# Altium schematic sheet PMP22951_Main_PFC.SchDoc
size 431 x 279 mm; Date: Not shown in title block; ApprovedBy: Not shown in title block; CheckedBy: Not shown in title block; Author: Not shown in title block; CompanyName: Not shown in title block; Engineer: Not shown in title block; Organization: Not shown in title block; Address1: Not shown in title block; Address2: Not shown in title block; Address3: Not shown in title block; Address4: Not shown in title block; DocumentNumber: 1; Revision: Use project parameter SCH_Rev; SheetNumber: 1; SheetTotal: 4; PageSetup: Record=PageOptions¦CenterHorizontal=True¦CenterVertical=True¦PrintScale=1.00¦XCorrection=1.00¦YCorrection=1.00¦PrintKind=0¦BorderSize=5000000¦LeftOffset=0¦BottomOffset=0¦Orientation=2¦PaperLength=1000¦PaperWidth=1000¦Scale=100¦PaperSource=15¦PrintQuality=600¦MediaType=1¦DitherType=10¦PaperKind=Letter¦PrintScaleMode=1
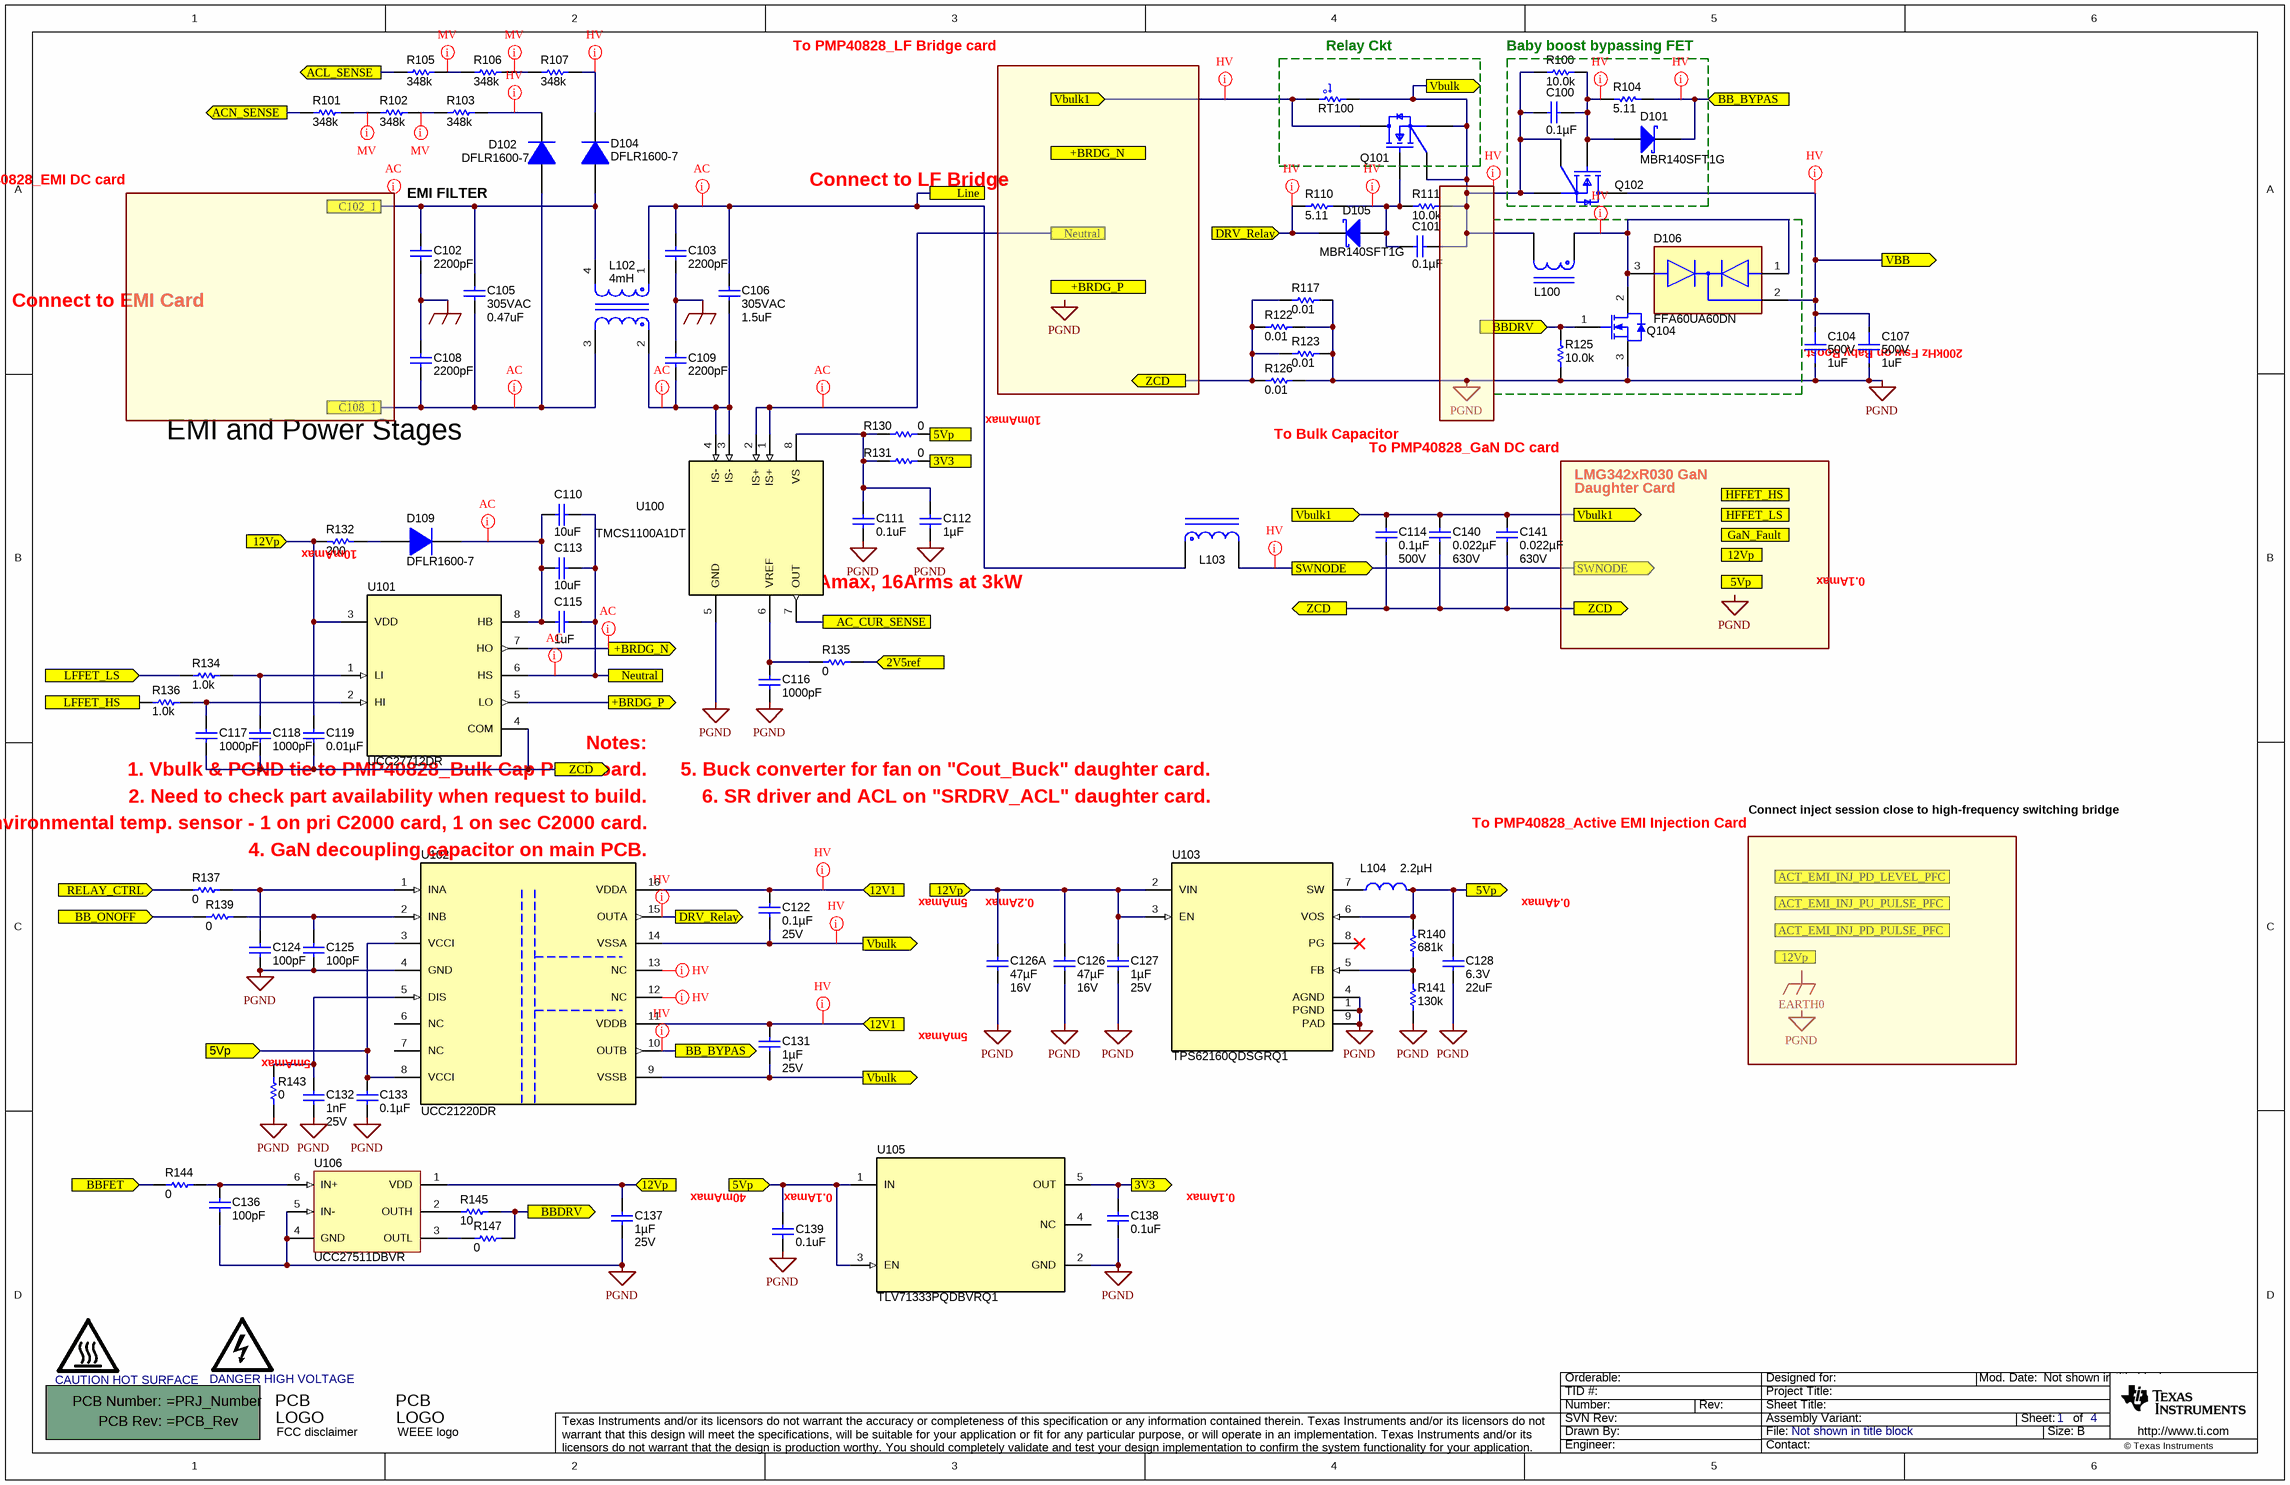
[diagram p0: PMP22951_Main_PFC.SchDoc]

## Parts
!PCB100  Printed Circuit Board  (value not drawn)  (mechanical)
C100  ValueDisplayed: 0.1µF  [0603]  (hidden comment: 06033C104JAT2A)
C101  ValueDisplayed: 0.1µF  [0603]  (hidden comment: 06033C104JAT2A)
C102  ValueDisplayed: 2200pF  [E_900x700x900]  (hidden comment: DE6E3KJ222MN3A)
C103  ValueDisplayed: 2200pF  [E_900x700x900]  (hidden comment: DE6E3KJ222MN3A)
C104  VDC_V: 500V  ValueDisplayed: 1uF  [FP-B58031U5105M062_SMD2-MFG]  (hidden comment: B58031U5105M062)
C105  Value2: 305VAC  ValueDisplayed: 0.47uF  [B32923_16.5mm_10.5]  (hidden comment: B32923H3474K000)
C106  Value2: 305VAC  ValueDisplayed: 1.5uF  [B32923_29.5mm]  (hidden comment: B32923H3155K000)
C107  VDC_V: 500V  ValueDisplayed: 1uF  [FP-B58031U5105M062_SMD2-MFG]  (hidden comment: B58031U5105M062)
C108  ValueDisplayed: 2200pF  [E_900x700x900]  (hidden comment: DE6E3KJ222MN3A)
C109  ValueDisplayed: 2200pF  [E_900x700x900]  (hidden comment: DE6E3KJ222MN3A)
C110  ValueDisplayed: 10uF  [0805_HV]  (hidden comment: 0805YD106MAT2A)
C111  ValueDisplayed: 0.1uF  [0402]  (hidden comment: GRM155R70J104KA01D)
C112  ValueDisplayed: 1µF  [0603]  (hidden comment: GRM185R60J105KE26D)
C113  ValueDisplayed: 10uF  [0805_HV]  (hidden comment: 0805YD106MAT2A)
C114  ValueDisplayed: 0.1µF  Value2: 500V  [1812]  (hidden comment: VJ1812Y104KXEAT5Z)
C115  ValueDisplayed: 1uF  [0603]  (hidden comment: C1608X7R1E105K080AB)
C116  ValueDisplayed: 1000pF  [0402]  (hidden comment: GRM155R60J102KA01D)
C117  ValueDisplayed: 1000pF  [0603]  (hidden comment: 06035A102KAT2A)
C118  ValueDisplayed: 1000pF  [0603]  (hidden comment: 06035A102KAT2A)
C119  ValueDisplayed: 0.01µF  [0603]  (hidden comment: C0603X103K5RACTU)
C122  ValueDisplayed: 0.1µF  Value2: 25V  [0603]  (hidden comment: 06033C104JAT2A)
C124  ValueDisplayed: 100pF  [0402]  (hidden comment: 0402YC101KAT2A)
C125  ValueDisplayed: 100pF  [0402]  (hidden comment: 0402YC101KAT2A)
C126  ValueDisplayed: 47µF  Value2: 16V  [1210_270]  (hidden comment: GRM32ER61C476KE15L)
C126A  ValueDisplayed: 47µF  Value2: 16V  [1210_270]  (hidden comment: GRM32ER61C476KE15L)
C127  Cap_F: 1µF  VDC_V: 25V  [0805_HV]  (hidden comment: C0805C105K3RACTU)
C128  VDC_V: 6.3V  ValueDisplayed: 22uF  [0805_HV]  (hidden comment: CL21A226KQQNNNE)
C131  ValueDisplayed: 1µF  Value2: 25V  [1206]  (hidden comment: C3216X7R1E105K085AA)
C132  Cap_F: 1nF  VDC_V: 25V  [0603]  (hidden comment: GRM188R71E102KA01D)
C133  ValueDisplayed: 0.1µF  [0402]  (hidden comment: 0402YC104KAT2A)
C136  ValueDisplayed: 100pF  [0402]  (hidden comment: 0402YC101KAT2A)
C137  ValueDisplayed: 1µF  Value2: 25V  [1206]  (hidden comment: C3216X7R1E105K085AA)
C138  ValueDisplayed: 0.1uF  [0402]  (hidden comment: GRM155R70J104KA01D)
C139  ValueDisplayed: 0.1uF  [0402]  (hidden comment: GRM155R70J104KA01D)
C140  ValueDisplayed: 0.022µF  Value2: 630V  [1206]  (hidden comment: CL31B223KHHNNNE)
C141  ValueDisplayed: 0.022µF  Value2: 630V  [1206]  (hidden comment: CL31B223KHHNNNE)
D101  MBR140SFT1G  [SOD-123FL]
D102  DFLR1600-7  [PowerDI123]
D104  DFLR1600-7  [PowerDI123]
D105  MBR140SFT1G  [SOD-123FL]
D106  FFA60UA60DN  [FP-FFA60UA60DN_SC-65-MFG]
D109  DFLR1600-7  [PowerDI123]
L100  PAL6281.104NL  [FP-PAL6281.104NL_PTH_20MM5_11MM0-MFG]  (value not drawn)
L102  Ind_H: 4mH  [FP-PAC6270NL_PTH_TRANSFORMER_30MM0_19MM0-MFG]  (hidden comment: PAC6270NL)
L103  PAL6269NL  [FP-PAL6269NL_PTH_32MM0_27MM8-MFG]  (value not drawn)
L104  Ind_H: 2.2µH  [FP-74438336010_SMD2-MFG]  (hidden comment: 74438336022)
LOGO100  CAUTION HOT SURFACE  [IEC_HotSurface_Small]  (no BOM)
LOGO101  DANGER HIGH VOLTAGE  [IEC_HighVoltage_Small]  (no BOM)
Logo102  FCC disclaimer  [FCC_disclaimer]  (no BOM)
Logo103  WEEE logo  [WEEE_Minimum]  (no BOM)
Q101  IPT60R022S7XTMA1  [FP-IPT60R080G7XTMA1_HSOF-8-MFG]  (value not drawn)
Q102  IPT60R022S7XTMA1  [FP-IPT60R080G7XTMA1_HSOF-8-MFG]  (value not drawn)
Q104  IPP60R060P7XKSA1  [TO-220AB]  (value not drawn)
R100  ValueDisplayed: 10.0k  [0603]  (hidden comment: CRCW060310K0FKEA)
R101  ValueDisplayed: 348k  [1206]  (hidden comment: RC1206FR-07348KL)
R102  ValueDisplayed: 348k  [1206]  (hidden comment: RC1206FR-07348KL)
R103  ValueDisplayed: 348k  [1206]  (hidden comment: RC1206FR-07348KL)
R104  ValueDisplayed: 5.11  [0603]  (hidden comment: CRCW06035R11FKEA)
R105  ValueDisplayed: 348k  [1206]  (hidden comment: RC1206FR-07348KL)
R106  ValueDisplayed: 348k  [1206]  (hidden comment: RC1206FR-07348KL)
R107  ValueDisplayed: 348k  [1206]  (hidden comment: RC1206FR-07348KL)
R110  ValueDisplayed: 5.11  [1206]  (hidden comment: CRCW12065R11FKEA)
R111  ValueDisplayed: 10.0k  [0603]  (hidden comment: CRCW060310K0FKEA)
R117  ValueDisplayed: 0.01  [1206]  (hidden comment: CSR1206FK10L0)
R122  ValueDisplayed: 0.01  [1206]  (hidden comment: CSR1206FK10L0)
R123  ValueDisplayed: 0.01  [1206]  (hidden comment: CSR1206FK10L0)
R125  ValueDisplayed: 10.0k  [0603]  (hidden comment: CRCW060310K0FKEA)
R126  ValueDisplayed: 0.01  [1206]  (hidden comment: CSR1206FK10L0)
R130  ValueDisplayed: 0  [0402]  (hidden comment: RC0402JR-070RL)
R131  ValueDisplayed: 0  [0402]  (hidden comment: RC0402JR-070RL)
R132  value 200  [0603]  (hidden comment: CRCW0603200RFKEA)
R134  value 1.0k  [0402]  (hidden comment: CRCW04021K00JNED)
R135  ValueDisplayed: 0  [0402]  (hidden comment: RC0402JR-070RL)
R136  value 1.0k  [0402]  (hidden comment: CRCW04021K00JNED)
R137  ValueDisplayed: 0  [0402]  (hidden comment: CRCW04020000Z0ED)
R139  ValueDisplayed: 0  [0402]  (hidden comment: CRCW04020000Z0ED)
R140  ValueDisplayed: 681k  [0402]  (hidden comment: CRCW0402681KFKED)
R141  ValueDisplayed: 130k  [0402]  (hidden comment: CRCW0402130KFKED)
R143  ValueDisplayed: 0  [0603]  (hidden comment: CRCW06030000Z0EA)
R144  ValueDisplayed: 0  [0402]  (hidden comment: CRCW04020000Z0ED)
R145  ValueDisplayed: 10  [0603]  (hidden comment: CRCW060310R0JNEAHP)
R147  ValueDisplayed: 0  [0603]  (hidden comment: CRCW06030000Z0EA)
RT100  B59751B0120A070  [TDK_B751]  (value not drawn)
U100  TMCS1100A1DT  [D0008A_N]
U101  UCC27712DR  [D0008A_N]
U102  UCC21220DR  [D0016B]
U103  TPS62160QDSGRQ1  [DSG0008A]
U105  TLV71333PQDBVRQ1  [DBV0005A_N]
U106  UCC27511DBVR  [DBV0006A_N]

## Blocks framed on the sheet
Relay Ckt: Q101 RT100
Baby boost bypassing FET: C100 D101 Q102 R100 R104

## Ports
2V5ref (in), 3V3 (in), 3V3 (out), 5Vp (in), 5Vp (out), 12V1 (in), 12Vp (in), +BRDG_N (in), +BRDG_N (out), +BRDG_P (in), +BRDG_P (out), AC_CUR_SENSE, ACL_SENSE (out), ACN_SENSE (out), ACT_EMI_INJ_PD_LEVEL_PFC (in), ACT_EMI_INJ_PD_PULSE_PFC (in), ACT_EMI_INJ_PU_PULSE_PFC (in), BB_BYPAS (in), BB_BYPAS (out), BB_ONOFF (in), BBDRV (in), BBDRV (out), BBFET (in), C102_1, C108_1, DRV_Relay (in), DRV_Relay (out), GaN_Fault (out), HFFET_HS (in), HFFET_LS (in), LFFET_HS (in), LFFET_LS (in), Line, Neutral, RELAY_CTRL (in), SWNODE (out), VBB (out), Vbulk1 (in), Vbulk1 (out), Vbulk (out), ZCD (out)

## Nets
EARTH0: C102.2 C108.1
EARTH1: C103.2 C109.1
PGND: C104.1 C107.1 C111.2 C112.2 C116.2 C124.2 C125.2 C126.1 C126A.1 C127.2 C128.2 C132.2 C133.2 C136.2 C137.2 C138.2 C139.2 Q104.3(S) R117.2 R122.2 R123.2 R125.1 R126.2 R141.1 R143.1 U100.5(GND) U102.4(GND) U103.1(PGND) U103.4(AGND) U103.9(PAD) U105.2(GND) U106.4(GND) U106.5(IN-)
2V5ref: R135.2 ; port 2V5ref
3V3: C138.1 R131.2 U105.5(OUT) ; port 3V3
5Vp: C128.1 C133.1 C139.1 L104.2 R130.2 R140.2 U102.3(VCCI) U102.8(VCCI) U103.6(VOS) U105.1(IN) U105.3(EN) ; port 5Vp
12V1: C122.2 C131.1 U102.11(VDDB) U102.16(VDDA) ; port 12V1
12Vp: C119.1 C126.2 C126A.2 C127.1 C137.1 R132.2 U101.3(VDD) U103.2(VIN) U103.3(EN) U106.1(VDD) ; port 12Vp
+BRDG_N: U101.7(HO) ; port +BRDG_N
+BRDG_P: U101.5(LO) ; port +BRDG_P
AC_CUR_SENSE: U100.7(OUT) ; port AC_CUR_SENSE
ACL_SENSE: R105.1 ; port ACL_SENSE
ACN_SENSE: R101.1 ; port ACN_SENSE
BB_BYPAS: D101.1(K) R104.2 U102.10(OUTB) ; port BB_BYPAS
BB_ONOFF: R139.1 ; port BB_ONOFF
BBDRV: Q104.1(G) R125.2 R145.1 R147.2 ; port BBDRV
BBFET: R144.1 ; port BBFET
C102_1: C102.1 C105.1 D104.2(A) L102.4 ; port C102_1
C108_1: C105.2 C108.2 D102.2(A) L102.3 ; port C108_1
DRV_Relay: D105.1(K) R110.1 U102.15(OUTA) ; port DRV_Relay
LFFET_HS: R136.1 ; port LFFET_HS
LFFET_LS: R134.1 ; port LFFET_LS
Line: C103.1 C106.1 L102.1 L103.1 ; port Line
Neutral: C110.2 C113.2 C115.1 U100.1(IS+) U100.2(IS+) U101.6(HS) ; port Neutral
RELAY_CTRL: R137.1 ; port RELAY_CTRL
SWNODE: L103.2 ; port SWNODE
VBB: C104.2 C107.2 D106.2(COMMON_CATHODE) Q102.9(Drain) ; port VBB
Vbulk: C100.2 C101.1 C122.1 C131.2 L100.2(F) Q101.2(Driver_Source) Q101.3-4-5-6-7-8(Source) Q102.2(Driver_Source) Q102.3-4-5-6-7-8(Source) R100.1 R111.2 RT100.1 U102.9(VSSB) U102.14(VSSA) ; port Vbulk
Vbulk1: C114.1 C140.1 C141.1 Q101.9(Drain) RT100.2 ; port Vbulk1
ZCD: C114.2 C117.2 C118.2 C119.2 C140.2 C141.2 R117.1 R122.1 R123.1 R126.1 U101.4(COM) ; port ZCD
NetC100_1: C100.1 D101.2(A) Q102.1(Gate) R100.2 R104.1
NetC101_2: C101.2 D105.2(A) Q101.1(Gate) R110.2 R111.1
NetC106_2: C106.2 C109.2 L102.2 U100.3(IS-) U100.4(IS-)
NetC110_1: C110.1 C113.1 C115.2 D109.1(K) U101.8(HB)
NetC111_1: C111.1 C112.1 R130.1 R131.1 U100.8(VS)
NetC116_1: C116.1 R135.1 U100.6(VREF)
NetC117_1: C117.1 R136.2 U101.2(HI)
NetC118_1: C118.1 R134.2 U101.1(LI)
NetC124_1: C124.1 R137.2 U102.1(INA)
NetC125_1: C125.1 R139.2 U102.2(INB)
NetC132_1: C132.1 R143.2 U102.5(DIS)
NetC136_1: C136.1 R144.2 U106.6(IN+)
NetD102_1: D102.1(K) R103.2
NetD104_1: D104.1(K) R107.2
NetD106_1: D106.1(1_ANODE) D106.3(2_ANODE) L100.1(S) Q104.2(D)
NetD109_2: D109.2(A) R132.1
NetL104_1: L104.1 U103.7(SW)
NetR101_2: R101.2 R102.1
NetR102_2: R102.2 R103.1
NetR105_2: R105.2 R106.1
NetR106_2: R106.2 R107.1
NetR140_1: R140.1 R141.2 U103.5(FB)
NetR145_2: R145.2 U106.2(OUTH)
NetR147_1: R147.1 U106.3(OUTL)

Not connected (* = marked no-connect by the designer): U102 6(NC) 7(NC) 12(NC) 13(NC); U103 8(PG)*; U105 4(NC)

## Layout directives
net class AC: +BRDG_N, C102_1, C108_1, Line, NetC106_2, NetC110_1, Neutral
net class HV: 12V1, BB_BYPAS, DRV_Relay, NetC100_1, NetC101_2, NetD102_1, NetD104_1, NetD106_1, NetU102_12, NetU102_13, SWNODE, VBB, Vbulk, Vbulk1
net class MV: NetR101_2, NetR102_2, NetR105_2, NetR106_2

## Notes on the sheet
- To PMP40828_LF Bridge card
- To PMP40828_EMI DC card
- EMI FILTER
- Connect to LF Bridge
- Connect to EMI Card
- (near C104) 200kHz Fsw on Baby Boost.
- 10mAmax
- To Bulk Capacitor
- (near C108) EMI and Power Stages
- To PMP40828_GaN DC card
- LMG342xR030 GaN
- Daughter Card
- (near R132) 10mAmax
- (near L103) 200uH, 25Amax, 16Arms at 3kW
- 0.1Amax
- Notes:
- 1. Vbulk & PGND tie to PMP40828_Bulk Cap PCB board.
- 5. Buck converter for fan on "Cout_Buck" daughter card.
- 2. Need to check part availability when request to build.
- 3. Need environmental temp. sensor - 1 on pri C2000 card, 1 on sec C2000 card.
- 6. SR driver and ACL on "SRDRV_ACL" daughter card.
- To PMP40828_Active EMI Injection Card
- Connect inject session close to high-frequency switching bridge
- 4. GaN decoupling capacitor on main PCB.
- 5mAmax
- (near C126A) 0.2Amax
- 0.4Amax
- (near R143) 5mAmax
- (near C137) 40mAmax
- (near C139) 0.1Amax
- (near C138) 0.1Amax
- Labels drawn without touching a wire or pin: EARTH0, PGND

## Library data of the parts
!PCB100 = CMP-0003618-2: Manufacturer: Any
C100 C101 C122 = 06033C104JAT2A: CAP, CERM, 0.1uF, 25V, +/-5%, X7R, 0603; Manufacturer: AVX; Polarized: N; CompType: Capacitor; U/M: EA; Cap_F: 0.0000001; Tolerance_%: 5; ESR_Ohm: 0.05; Value1: 0.05 ohm; VDC_V: 25; TaMin_C: -55; TaMax_C: 125
C102 C103 C108 C109 = DE6E3KJ222MN3A: CAP, CERM, 2200 pF, 300 V, +/- 20%, E, TH, 2- Leads, Body 9x7mm, Pin Spacing 7.5mm; Manufacturer: MuRata; Polarized: N; CompType: Capacitor; Value: 2200pF; U/M: EA; Cap_F: 0.0000000022; Tolerance_%: 20; Value1: Unknown; VDC_V: 300; Value2: 300V; TaMin_C: -40; TaMax_C: 125; Cap_Case: 9x7x9mm; SizeArea_mm2: 63; SizeAreaWB_mm2: 99; SizeX_mm: 9; SizeY_mm: 7; SizeZ_mm: 12; AEC Category: Q200
C104 C107 = CMP-0091050-1: TDK 1µF Multilayer Ceramic Capacitor MLCC 500V dc ±20% SMD; AEC Grade: Grade 0; AEC Qualified: Yes; SizeZ_mm: 4.5mm
C105 = CMP-0012429-3: CAP FILM 0.47UF 10% 630VDC RAD; Manufacturer: TDK; Polarized: N; SizeAreaWB_mm2: 356.25; Value1: Unknown; TaMax_C: 110°C; Tolerance_%: 20%; SizeZ_mm: 16.5; SizeX_mm: 26.5; SizeY_mm: 10.5; SizeArea_mm2: 278.25; CompType: Capacitor; Cap_F: 470nF; VDC_V: 630V; AEC Category: Q200
C106 = CMP-0012424-1: CAP FILM 1.5UF 10% 630VDC RADIAL; Manufacturer: TDK; Polarized: N; SizeAreaWB_mm2: 470.25; Value1: Unknown; U/M: EA; TaMax_C: 110°C; Tolerance_%: 20%; SizeZ_mm: 29.5; SizeX_mm: 26.5; SizeY_mm: 14.5; SizeArea_mm2: 384.25; CompType: Capacitor; Cap_F: 1.5µF; VDC_V: 630V; AEC Category: Q200
C110 C113 = 0805YD106MAT2A: CAP, CERM, 10uF, 16V, +/-20%, X5R, 0805; Manufacturer: AVX; Polarized: N; CompType: Capacitor; U/M: EA; Cap_F: 0.00001; Tolerance_%: 20; Value1: Unknown; VDC_V: 16; TaMin_C: -55; TaMax_C: 85; Cap_Case: 0805
C111 C138 C139 = GRM155R70J104KA01D: CAP, CERM, 0.1uF, 6.3V, +/-10%, X7R, 0402; Manufacturer: MuRata; Polarized: N; CompType: Capacitor; U/M: EA; Cap_F: 0.0000001; Tolerance_%: 10; Value1: Unknown; VDC_V: 6.3; TaMin_C: -55; TaMax_C: 125
C112 = GRM185R60J105KE26D: CAP, CERM, 1uF, 6.3V, +/-10%, X5R, 0603; Manufacturer: MuRata; Polarized: N; CompType: Capacitor; U/M: EA; Cap_F: 0.000001; Tolerance_%: 10; Value1: Unknown; VDC_V: 6.3; TaMin_C: -55; TaMax_C: 85
C114 = VJ1812Y104KXEAT5Z: CAP, CERM, 0.1 µF, 500 V,+/- 10%, X7R, 1812; Manufacturer: Vishay-Vitramon; Polarized: N; CompType: Capacitor; Value: 0.1uF; U/M: EA; Cap_F: 0.0000001; Tolerance_%: 10; VDC_V: 500; TaMin_C: -55; TaMax_C: 125; SizeArea_mm2: 14.4; SizeAreaWB_mm2: 23.1; SizeX_mm: 4.5; SizeY_mm: 3.2; SizeZ_mm: 1.35; AEC Category: Q200
C115 = C1608X7R1E105K080AB: CAP, CERM, 1uF, 25V, +/-10%, X7R, 0603; Manufacturer: TDK; Polarized: N; CompType: Capacitor; U/M: EA; Cap_F: 0.000001; Tolerance_%: 10; Value1: Unknown; VDC_V: 25; TaMin_C: -55; TaMax_C: 125
C116 = GRM155R60J102KA01D: CAP, CERM, 1000pF, 6.3V, +/-10%, X5R, 0402; Manufacturer: MuRata; Polarized: N; CompType: Capacitor; U/M: EA; Cap_F: 0.000000001; Tolerance_%: 10; Value1: Unknown; VDC_V: 6.3; TaMin_C: -55; TaMax_C: 85
C117 C118 = 06035A102KAT2A: CAP, CERM, 1000 pF, 50 V, +/- 10%, C0G/NP0, 0603; Manufacturer: AVX; Polarized: N; CompType: Capacitor; Value: 1000pF; U/M: EA; Cap_F: 0.000000001; Tolerance_%: 10; ESR_ohm: 0.048; Value1: 0.048 ohm; VDC_V: 50; Value2: 50V; TaMin_C: -55; TaMax_C: 125; SizeArea_mm2: 1.28; SizeAreaWB_mm2: 4.68; SizeX_mm: 1.6; SizeY_mm: 0.8; SizeZ_mm: 1; AEC Category: Q200
C119 = C0603X103K5RACTU: CAP, CERM, 0.01uF, 50V, +/-10%, X7R, 0603; Manufacturer: Kemet; Polarized: N; CompType: Capacitor; U/M: EA; Cap_F: 0.00000001; Tolerance_%: 10; Value1: Unknown; VDC_V: 50; TaMin_C: -55; TaMax_C: 125
C124 C125 C136 = 0402YC101KAT2A: CAP, CERM, 100 pF, 16 V,+/- 10%, X7R, 0402; Manufacturer: AVX; Polarized: N; CompType: Capacitor; Value: 100pF; U/M: EA; Cap_F: 0.0000000001; Tolerance_%: 10; VDC_V: 16; Value2: 16V; TaMin_C: -55; TaMax_C: 125; SizeArea_mm2: 0.5; SizeAreaWB_mm2: 3; SizeX_mm: 1; SizeZ_mm: 0.6; AEC Category: Q200
C126 C126A = GRM32ER61C476KE15L: CAP, CERM, 47 µF, 16 V, +/- 10%, X5R, 1210; Manufacturer: MuRata; Polarized: N; CompType: Capacitor; Value: 47uF; U/M: EA; Cap_F: 0.000047; Tolerance_%: 10; Value1: Unknown; VDC_V: 16; TaMin_C: -55; TaMax_C: 85; Cap_Case: 1210; SizeArea_mm2: 8; SizeAreaWB_mm2: 14.7; SizeX_mm: 3.2; SizeY_mm: 2.5; SizeZ_mm: 2.7; AEC Category: Q200
C127 = CMP-0007728-2: CAP, CERM, 1 uF, 25 V, +/- 10%, X7R, 0805; Manufacturer: Kemet; TaMin_C: -55°C; Polarized: N; SizeAreaWB_mm2: 6.75; Value1: Unknown; U/M: EA; Value: 1uF; TaMax_C: 125°C; SizeZ_mm: 1.45; SizeX_mm: 2; SizeY_mm: 1.25; Cap_Case: 0805; SizeArea_mm2: 2.5; AEC Category: Q200
C128 = CMP-0007989-2: CAP, CERM, 22 uF, 6.3 V, +/- 10%, X5R, 0805; Manufacturer: Samsung Electro-Mechanics; TaMin_C: -55°C; Polarized: N; SizeAreaWB_mm2: 6.75; Value1: Unknown; U/M: EA; Value: 22uF; TaMax_C: 85°C; SizeZ_mm: 1.45; SizeX_mm: 2; SizeY_mm: 1.25; Cap_Case: 0805; SizeArea_mm2: 2.5; Cap_F: 22µF; AEC Category: Q200
C131 C137 = C3216X7R1E105K085AA: CAP, CERM, 1 µF, 25 V,+/- 10%, X7R, 1206; Manufacturer: TDK; Polarized: N; CompType: Capacitor; Value: 1uF; U/M: EA; Cap_F: 0.000001; Tolerance_%: 10; ESR_ohm: 0.01; Value1: 0.01 ohm; VDC_V: 25; TaMin_C: -55; TaMax_C: 125; SizeArea_mm2: 5.12; SizeAreaWB_mm2: 10.92; SizeX_mm: 3.2; SizeY_mm: 1.6; SizeZ_mm: 1.35; AEC Category: Q200; Green_Lifecycle: NRND; Green_REACh: Passed
C132 = CMP-0007402-1: CAP, CERM, 1000 pF, 25 V, +/- 10%, X7R, 0603; Manufacturer: MuRata; TaMin_C: -55°C; Polarized: N; SizeAreaWB_mm2: 4.68; Value1: Unknown; U/M: EA; Value: 1000pF; TaMax_C: 125°C; SizeZ_mm: 1; SizeX_mm: 1.6; SizeY_mm: 0.8; SizeArea_mm2: 1.28; AEC Category: Q200
C133 = 0402YC104KAT2A: CAP, CERM, 0.1 µF, 16 V,+/- 10%, X7R, 0402; Manufacturer: AVX; Polarized: N; CompType: Capacitor; Value: 0.1uF; U/M: EA; Cap_F: 0.0000001; Tolerance_%: 10; VDC_V: 16; Value2: 16V; TaMin_C: -55; TaMax_C: 125; SizeArea_mm2: 0.5; SizeAreaWB_mm2: 3; SizeX_mm: 1; SizeZ_mm: 0.6; AEC Category: Q200; Green_Lifecycle: Active; Green_REACh: Passed
C140 C141 = VJ1206Y223KXGAT5Z: CAP, CERM, 0.022 µF, 630 V,+/- 10%, X7R, 1206; Manufacturer: Samsung Electro-Mechanics; Polarized: N; CompType: Capacitor; Value: 0.022uF; U/M: EA; Cap_F: 0.000000022; Tolerance_%: 10; VDC_V: 630; TaMin_C: -55; TaMax_C: 125; SizeArea_mm2: 5.12; SizeAreaWB_mm2: 10.92; SizeX_mm: 3.2; SizeY_mm: 1.6; SizeZ_mm: 1.35; AEC Category: Q200
D101 D105 = CMP-0028548-2: Diode, Schottky, 40 V, 1 A, SOD-123FL; Manufacturer: ON Semiconductor; SizeZ_mm: 0.98; Vf_V: 5.5dV; AEC Category: Q101; Green_REACh: Passed; SizeArea_mm2: 5.94; Vr_V: 40V; TJmax_C: 125°C; RJC_CperW: 26; Value1: 1A; SizeY_mm: 1.65; SizeX_mm: 3.6; Value: 40V; Value2: 0.55V; SizeAreaWB_mm2: 12.19; Green_Lifecycle: Active
D102 D104 D109 = CMP-0076978-2: Diode, Standard Recovery Rectifier, 600 V, 1 A, PowerDI123; Manufacturer: Diodes Inc.; AEC Category: Q101; SizeAreaWB_mm2: 13.066; SizeY_mm: 1.78; Value2: 1.1V; TJmax_C: 150°C; Green_Lifecycle: Not Set; Value1: 1A; Value: 600V; SizeZ_mm: 0.98; SizeX_mm: 3.7; SizeArea_mm2: 6.586; Green_REACh: Incomplete
D106 = CMP-0090872-1: Diode Array 1 Pair Common Cathode Standard 600V 30A Through Hole TO-3P-3, SC-65-3; Manufacturer: ON Semiconductor; Peak Reverse Current: 100uA; SizeZ_mm: 23.8mm; AEC Qualified: No; TJmax_C: 175°C; Max Surge Forward Current: 180A; Standoff Height: 3.3mm
L100 = CMP-0091020-1: Inductor Buck/Boost, Toroid, TH, 100uH 15% 8A; Manufacturer: Pulse Electronics; DCR_ohm: 1.08d; AEC Qualified: No; SizeZ_mm: 22.5mm; Test Frequency: 100kHz; Ind_H: 100µH
L102 = CMP-0091106-1: IND, CUR-SENSE, 4MH, 20A, TOR, TH; Manufacturer: Pulse Electronics; DCR_ohm: 6m; Voltage_Isolation_Vrms: 1500VDC; AEC Qualified: No; SizeZ_mm: 32mm; Rsec1_ohm: 6mΩ; Ns1toNp: 1:1
L103 = CMP-0091118-1: Inductor Power 300uH T27 THT; Manufacturer: Pulse Electronics; Tolerance_%: 15%; Test Frequency: 100kHz; Ind_H: 300µH; DCR_ohm: 0.075; SizeZ_mm: 30.5mm
L104 = CMP-0087867-1: 2.2µH Shielded Molded Inductor 2.4A 67mOhm Max 2-SMD; Manufacturer: Wurth Electronics; SizeZ_mm: 2mm; Material: Metal Composite; Isat: 4.3A; Symbol Name: SYM-74438336010; DCR_ohm: 0.032; AEC Grade: Grade 1; AEC Qualified: Yes
LOGO100 = CMP-0074837-1: IEC 61010-1 Hot Surface Warning; Library Reference: IEC_HotSurface; SymbolCreator: a0412235
LOGO101 = CMP-0074835-1: IEC 61010-1 High Voltage Warning; Library Reference: IEC_HighVoltage; SymbolCreator: a0412235
Logo102 = CMP-0074847-1: FCC_disclaimer; Library Reference: Logo
Logo103 = CMP-0074769-1
Q101 Q102 = CMP-0086487-1: N-Channel 600V 23A (Tc) 390W (Tc) Surface Mount PG-HSOF-8-2; Manufacturer: Infineon; VdsMax_V: 650V; IdsMax_A: 29A; Vgs_V: 20V; AEC Qualified: No; ChMode: False; SizeZ_mm: 2.4mm
Q104 = CMP-0001223-3: MOSFET N-CH 600V 48A TO220-3; Alternate Manufacturer: None; Manufacturer: Infineon Technologies; ChType: N; AEC Category: Q101; U/M: EA
R100 R111 R125 = CRCW060310K0FKEA: RES, 10.0 k, 1%, 0.1 W, 0603; Manufacturer: Vishay-Dale; CompType: Resistor; Value: 10.0k; Res_ohm: 10000; Value_Code: 10k0; Tolerance_%: 1; Power_W: 0.1; Value2: 0.1W; VDC_V: 75; TempCo: 100 ppm/C; SizeArea_mm2: 1.28; SizeX_mm: 1.6; SizeY_mm: 0.8; EIA_Code: E96; U/M: EA; AEC Category: Q200; Green_Lifecycle: Active; Green_REACh: Passed
R101-R103 R105-R107 = CMP-0018215-2: RES, 348 k, 1%, 0.25 W, 1206; Manufacturer: Yageo America; Power_W: 250mW; TempCo: 100 ppm/C; U/M: EA; Value: 348k; EIA_Code: E96; SizeX_mm: 3.2; SizeY_mm: 1.6; SizeZ_mm: 1.35; Value2: 0.25W; SizeArea_mm2: 5.12; VDC_V: 200V; AEC Category: Q200
R104 = CRCW06035R11FKEA: RES, 5.11, 1%, 0.1 W, 0603; Manufacturer: Vishay-Dale; CompType: Resistor; Value: 5.11; Value_Code: 5R11; Tolerance_%: 1; Power_W: 0.1; Value2: 0.1W; VDC_V: 75; TempCo: 100 ppm/C; SizeArea_mm2: 1.28; SizeX_mm: 1.6; SizeY_mm: 0.8; EIA_Code: E96; U/M: EA; AEC Category: Q200; Green_Lifecycle: Active; Green_REACh: Passed
R110 = CRCW12065R11FKEA: RES, 5.11, 1%, 0.25 W, 1206; Manufacturer: Vishay-Dale; CompType: Resistor; Value: 5.11; Value_Code: 5R11; Tolerance_%: 1; Power_W: 0.25; Value2: 0.25W; VDC_V: 200; TempCo: 100 ppm/C; SizeArea_mm2: 5.12; SizeX_mm: 3.2; SizeY_mm: 1.6; SizeZ_mm: 1.35; EIA_Code: E96; U/M: EA; AEC Category: Q200
R117 R122 R123 R126 = CSR1206FK10L0: RES, 0.01, 1%, 0.5 W, 1206; Manufacturer: Stackpole Electronics Inc; CompType: Resistor; Value: 0.01; Value_Code: R010; Tolerance_%: 1; Power_W: 0.5; Value2: 0.5W; TempCo: 100 ppm/C; SizeArea_mm2: 5.12; SizeX_mm: 3.2; SizeY_mm: 1.6; SizeZ_mm: 1.35; EIA_Code: E96; U/M: EA; AEC Category: Q200
R130 R131 R135 = CMP-0027004-2: RES, 0, 5%, 0.063 W, 0402; Manufacturer: Yageo America; Power_W: 63mW; TempCo: 200 ppm/C; Value_Code: 0000; U/M: EA; Value: 0; EIA_Code: E24; SizeX_mm: 1; SizeY_mm: 0.5; SizeZ_mm: 0.6; Value2: 0.063W; VDC_V: 50V; AEC Category: Q200
R132 = CRCW0603200RFKEA: RES, 200 ohm, 1%, 0.1W, 0603; Manufacturer: Vishay-Dale; CompType: Resistor; Value_Code: 200R; Tolerance_%: 1; Power_W: 0.1; VDC_V: 75; TempCo: 100 ppm/C; EIA_Code: E96; U/M: EA
R134 R136 = CRCW04021K00JNED: RES, 1.0k ohm, 5%, 0.063W, 0402; Manufacturer: Vishay-Dale; CompType: Resistor; Res_ohm: 1000; Value_Code: 1k00; Tolerance_%: 5; Power_W: 0.063; VDC_V: 50; TempCo: 200 ppm/C; EIA_Code: E24; U/M: EA
R137 R139 R144 = CRCW04020000Z0ED: RES, 0, 5%, 0.063 W, 0402; Manufacturer: Vishay-Dale; CompType: Resistor; Value: 0; Value_Code: 0000; Tolerance_%: 5; Power_W: 0.063; Value2: 0.063W; VDC_V: 50; TempCo: 200 ppm/C; SizeArea_mm2: 0.5; SizeX_mm: 1; SizeZ_mm: 0.6; EIA_Code: E24; U/M: EA; AEC Category: Q200; Green_Lifecycle: Active; Green_REACh: Passed
R140 = CMP-0026504-2: RES, 681 k, 1%, 0.063 W, AEC-Q200 Grade 0, 0402; Manufacturer: Vishay-Dale; Power_W: 63mW; TempCo: 100 ppm/C; Value: 681k; EIA_Code: E96; SizeX_mm: 1; SizeY_mm: 0.5; SizeZ_mm: 0.6; Value2: 0.063W; AEC Qualified: Y; VDC_V: 50V; AEC Category: Q200; AEC Grade: 0
R141 = CMP-0025997-3: RES, 130 k, 1%, 0.063 W, AEC-Q200 Grade 0, 0402; Manufacturer: Vishay-Dale; Power_W: 63mW; TempCo: 100 ppm/C; Value: 130k; EIA_Code: E96; SizeX_mm: 1; SizeY_mm: 0.5; SizeZ_mm: 0.6; Value2: 0.063W; AEC Qualified: Y; VDC_V: 50V; AEC Category: Q200; AEC Grade: 0
R143 R147 = CRCW06030000Z0EA: RES, 0, 5%, 0.1 W, 0603; Manufacturer: Vishay-Dale; CompType: Resistor; Value: 0; Value_Code: 0000; Tolerance_%: 5; Power_W: 0.1; Value2: 0.1W; VDC_V: 75; TempCo: 200 ppm/C; EIA_Code: E24; U/M: EA; AEC Category: Q200
R145 = CRCW060310R0JNEAHP: RES, 10, 5%, 0.25 W, 0603; Manufacturer: Vishay-Dale; CompType: Resistor; Value: 10; Value_Code: 10R0; Tolerance_%: 5; Power_W: 0.25; Value2: 0.25W; VDC_V: 75; TempCo: 200 ppm/C; EIA_Code: E24; U/M: EA
RT100 = B59751B0120A070: Thermistor PTC, 50 ohm, 25%, D12.5xH16.5mm; Manufacturer: TDK; CompType: ThermistorNTC; Value: 50 ohm; Tolerance_%: 25; TaMin_C: -40; TaMax_C: 125; U/M: EA
U100 = CMP-0081537-2: TMCS1100A1DT, D0008A (SOIC-8); Alternate Manufacturer: Texas Instruments; CompType: IC; SizeAreaWB_mm2: 56.58; SizeX_mm: 4.9; SizeY_mm: 6.2; AEC Category: Q200; SizeArea_mm2: 30.38; SizeZ_mm: 1.75; AEC Qualified: N
U101 = CMP-0013005-2: 620-V High-Side Low-Side Gate Driver with 2.5A Peak Output and RobustDrive, D0008A (SOIC-8); Manufacturer: Texas Instruments; SizeX_mm: 4.9; SizeY_mm: 6.2; CompType: IC; SizeZ_mm: 1.75; SizeArea_mm2: 30.38; SizeAreaWB_mm2: 56.58; U/M: EA
U102 = CMP-0077646-2: 4-A, 6-A, 3.0-kVRMS Isolated Dual-Channel Gate Driver, D0016B (SOIC-16); Alternate Manufacturer: Texas Instruments; SizeAreaWB_mm2: 95.2; SizeZ_mm: 1.75; SizeX_mm: 6.0; SizeY_mm: 9.9; SizeArea_mm2: 59.4; CompType: IC; AEC Qualified: N; AEC Category: Q200; Rating: Catalog
U103 = CMP-0067100-2: 3V-17V 1A Automotive Step-Down Converters in 2x2SON, DSG0008A (WSON-8); Alternate PartNumber: TPS62160QDSGTQ1; Manufacturer: Texas Instruments; SizeZ_mm: 0.8; SizeX_mm: 2.0; SizeArea_mm2: 4.0; CompType: IC; U/M: EA; SizeAreaWB_mm2: 9.0
U105 = TLV71333PQDBVRQ1: Capacitor-Free, 150-mA, Low-Dropout Regulator with Foldback Current Limit for Portable Devices, DBV0005A; Manufacturer: Texas Instruments; SymbolCreator: Altium; SizeArea_mm2: 8.12; SizeAreaWB_mm2: 14.82; SizeX_mm: 2.8; SizeY_mm: 2.9; SizeZ_mm: 1.45; CompType: IC; U/M: EA
U106 = UCC27511DBVR: Single-Channel High-Speed Low-Side Gate Driver (with 4-A Peak Source and 8-A Peak Sink), DBV0006A; Alternate PartNumber: UCC27511DBVT; Manufacturer: Texas Instruments; SymbolCreator: a0411947; CompType: IC; U/M: EA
